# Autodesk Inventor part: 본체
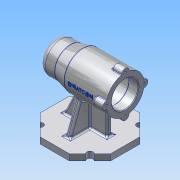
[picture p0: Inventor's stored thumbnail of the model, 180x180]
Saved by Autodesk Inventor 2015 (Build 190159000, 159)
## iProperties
Created: 2019-12
Part Number: 본체
Material: 알루미늄 6061
Document SubType Name: Modeling
Designer: user
Density: 2.7 g/cm^3
Appearance: 알루미늄 - 평지
Mass: 725.94 g
Surface Area: 714.643 cm^2
Volume: 268.867 cm^3
Author: user
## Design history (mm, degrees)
sketch "스케치2"
  geometry: L1 (-80.885, 0)-(78.814, 0) reference; L2 (0, -6)-(0, 36) reference; L3 (-56, 0)-(56, 0); L4 (-56, 0)-(-31, 0); L5 (-31, 0)-(-31, 25); L6 (-31, 25)-(-46, 25); L7 (-56, 15)-(-56, 0); L8 (-31, 0)-(-11, 0); L9 (-11, 0)-(-11, 30); L10 (-31, 25)-(-31, 0); L11 (-11, 0)-(56, 0); L12 (56, 0)-(56, 30); L13 (56, 30)-(-11, 30); L14 (-11, 30)-(-11, 0); L15 (-31, 25)-(-11, 30); A1 r 10 centre (-46, 15) between (-46, 25) and (-56, 15); 2 further points
  constraints: 26 end point, 5 parallel, 4 horizontal, 3 perpendicular, 2 point on circle, 2 point on line, 2 tangent, 1 centre point, 1 collinear, 1 symmetric about line
  dimensions: "d0" = 112 distance of L3.start L3.end; "d1" = 50 diameter of L6 L3; "d2" = 25 distance of L5.end point (-56, 25); "d3" = 45 distance between parallel lines of L7 L9; "d6" = 60 diameter of L9.end L3; "d7" = 112 distance between parallel lines of L7 L12; "d8" = 10 radius of A1
revolve "회전1" sketch "스케치2" stored, may be unused: angle "d9" = 90 deg
sketch "스케치3"
  geometry: L1 (-56, -15)-(-56, 15) reference; L2 (-46, 25)-(-31, 25) reference; L3 (-31, 25)-(-11, 30) reference; L4 (-11, 30)-(56, 30) reference; L5 (56, 30)-(56, -30) reference; L6 (56, -30)-(-11, -30) reference; L7 (-11, -30)-(-31, -25) reference; L8 (-31, -25)-(-46, -25) reference; L9 (-80.885, 0)-(78.814, 0) reference; L10 (-56, 0)-(56, 0); L11 (56, 0)-(41, 0); L12 (41, 0)-(41, 21); L13 (41, 21)-(56, 21); L14 (56, 21)-(56, 0); L15 (41, 0)-(-13, 0); L16 (-13, 0)-(-13, 21); L17 (-10, 24)-(38, 24); L18 (41, 21)-(41, 0); L19 (-13, 0)-(-25, 0); L20 (-25, 0)-(-25, 20.7); L21 (-24.7, 21)-(-13, 21); L22 (-13, 21)-(-13, 0); L23 (-25, 0)-(-43, 0); L24 (-43, 0)-(-43, 17.2); L25 (-42.7, 17.5)-(-25, 17.5); L26 (-25, 17.5)-(-25, 0); L27 (-43, 0)-(-47, 0); L28 (-47, 0)-(-47, 15.7); L29 (-46.7, 16)-(-43, 16); L30 (-43, 16)-(-43, 0); L31 (-47, 0)-(-50, 0); L32 (-50, 0)-(-50, 7.5); L33 (-47, 10.5)-(-47, 10.5); L34 (-47, 10.5)-(-47, 0); A1 r 10 centre (-46, 15) between (-46, 25) and (-56, 15) reference; A2 r 10 centre (-46, -15) between (-56, -15) and (-46, -25) reference; A3 r 0.3 centre (-46.7, 15.7) between (-46.7, 16) and (-47, 15.7); A4 r 0.3 centre (-42.7, 17.2) between (-42.7, 17.5) and (-43, 17.2); A5 r 0.3 centre (-24.7, 20.7) between (-24.7, 21) and (-25, 20.7); A6 r 3 centre (-47, 7.5) between (-47, 10.5) and (-50, 7.5); A7 r 3 centre (-10, 21) between (-10, 24) and (-13, 21); A8 r 3 centre (38, 21) between (41, 21) and (38, 24); 7 further points
  constraints: 50 end point, 12 parallel, 12 point on circle, 12 point on line, 12 tangent, 7 perpendicular, 6 centre point, 6 horizontal, 4 equal radius, 2 midpoint, 1 collinear
  dimensions: "d11" = 42 diameter of L13 L9; "d12" = 48 diameter of L17 L9; "d13" = 15 distance of L12.end L13.end; "d14" = 54 distance of point (-13, 24) point (41, 24); "d15" = 12 distance of point (-25, 21) L21.end; "d16" = 42 diameter of L21 L9; "d17" = 18 distance of point (-43, 17.5) L25.end; "d18" = 35 diameter of L25 L9; "d19" = 32 diameter of L29 L9; "d20" = 21 diameter of L33 L10; "d21" = 3 distance of point (-50, 10.5) L33.end; "d22" = 4 distance of point (-47, 16) L29.end; "d23" = 0.3 radius of A3; "d24" = 3 radius of A6
revolve "회전2" sketch "스케치3" stored, may be unused: angle "d25" = 90 deg
node "작업 평면1"
sketch "스케치4"
  geometry: L1 (0, -42)-(0, 42) reference; L2 (78.4, 0)-(-78.4, 0) reference; L3 (23.196, -56)-(-23.196, -56); L4 (-56, -23.196)-(-56, 23.196); L5 (-23.196, 56)-(23.196, 56); L6 (56, 23.196)-(56, -23.196); L7 (56, 23.196)-(23.196, 56); L8 (-56, 23.196)-(-23.196, 56); L9 (56, -23.196)-(23.196, -56); L10 (-56, -23.196)-(-23.196, -56); C1 r 56 at (0, 0); 1 further point
  constraints: 16 end point, 6 symmetric about line, 5 tangent, 2 parallel, 1 centre point, 1 coincident, 1 horizontal, 1 perpendicular
  dimensions: "d28" = 112 diameter of C1; "d30" = 45 deg angle of L7 L2
extrude "돌출1" join sketch "스케치4" distance "d31" = 10; taper "d32" = 0 deg
sketch "스케치5" dims "d33" = 112
  geometry: L1 (-56, -23.196)-(-23.196, -56) reference; C1 r 5 at (-39.598, -39.598); C2 r 5 at (39.598, -39.598); C3 r 5 at (39.598, 39.598); C4 r 5 at (-39.598, 39.598); 2 further points
  constraints: 4 centre point, 1 coincident, 1 midpoint, 12 other
  dimensions: "d34" = 10 diameter of C1; "d37" = 360 deg dimension on point (0, 0) C1.centre (derived)
extrude "돌출2" cut sketch "스케치5" distance "d39" = 10; taper "d40" = 0 deg
sketch "스케치6"
  geometry: L1 (-56, 23.196)-(-56, -23.196) reference; L2 (56, -23.196)-(56, 23.196) reference; L3 (43.134, 36.062)-(56, 23.196) reference; L4 (56, 23.196)-(56, -23.196) reference; L5 (56, -23.196)-(43.134, -36.062) reference; L6 (36.062, -43.134)-(23.196, -56) reference; L7 (23.196, -56)-(-23.196, -56) reference; L8 (-23.196, -56)-(-36.062, -43.134) reference; L9 (-43.134, -36.062)-(-56, -23.196) reference; L10 (-56, -23.196)-(-56, 23.196) reference; L11 (-56, 23.196)-(-43.134, 36.062) reference; L12 (-36.062, 43.134)-(-23.196, 56) reference; L13 (-23.196, 56)-(23.196, 56) reference; L14 (23.196, 56)-(36.062, 43.134) reference; L15 (78.4, 0)-(-78.4, 0) reference; L16 (0, 78.4)-(0, -78.4) reference; L17 (31, -4)-(-38, -4); L18 (-38, -4)-(-38, 4); L19 (-38, 4)-(31, 4); L20 (31, 4)-(31, -4); A1 r 5 centre (39.598, 39.598) between (36.062, 43.134) and (43.134, 36.062) reference; A2 r 5 centre (39.598, -39.598) between (43.134, -36.062) and (36.062, -43.134) reference; A3 r 5 centre (-39.598, -39.598) between (-36.062, -43.134) and (-43.134, -36.062) reference; A4 r 5 centre (-39.598, 39.598) between (-43.134, 36.062) and (-36.062, 43.134) reference; 1 further point
  constraints: 8 end point, 2 parallel, 1 horizontal, 1 perpendicular, 1 other
  dimensions: "d41" = 8 distance of L19.end L17.start; "d42" = 18 distance between parallel lines of L1 L18; "d43" = 25 distance between parallel lines of L20 L2
extrude "돌출3" join sketch "스케치6" stored distance "d44" = 10; taper "d45" = 0 deg
feature "면 기울기1" dims angle "d46" = 25 deg
sketch "스케치8"
  geometry: L1 (-29.732, -4)-(-70, -4) reference; L2 (-70, -4)-(-70, -56) reference; L3 (-70, -56)-(-80, -56) reference; L4 (-80, -56)-(-80, 56) reference; L5 (-80, 56)-(-70, 56) reference; L6 (-70, 56)-(-70, 4) reference; L7 (-70, 4)-(-29.732, 4) reference; L8 (-70, 36)-(-23.234, 18.979); L9 (-102, 0)-(52, 0) reference; L10 (-70, 36)-(-70, 4); L11 (-70, 4)-(-29.732, 4); C1 r 24 at (0, 0) reference; A1 r 30 centre (0, 0) between (-29.732, -4) and (-29.732, 4) reference; A2 r 30 centre (0, 0) between (-23.234, 18.979) and (-29.732, 4); 1 further point
  constraints: 6 end point, 3 point on circle, 1 centre point, 1 perpendicular, 1 point on line, 1 vertical
  dimensions: "d50" = 110 deg angle of L8 L6; "d51" = 20 distance of L8.start L5.end; "d52" = 30 radius of A2
extrude "돌출4" join sketch "스케치8" stored distance "d53" = 8; taper "d54" = 0 deg
sketch "스케치9"
  geometry: L1 (0, -102)-(0, 52) reference; C1 r 6 at (0, 30); 1 further point
  constraints: 1 centre point, 1 point on line, 1 vertical alignment, 1 other
  dimensions: "d56" = 12 diameter of C1
extrude "돌출5" join sketch "스케치9" distance "d57" = 16; taper "d58" = 0 deg
hole "구멍1" diameter "d64" = 3.242; stored, may be unused: countersink angle "d68" = 90 deg, drill point angle "d70" = 118 deg; dims "d65" = 8, "d66" = 4, "d67" = 2, "d69" = 11, "d88" = 10, "d89" = 10
fillet "모깎기1" dims "d74" = 3
fillet "모깎기2" dims "d75" = 1
fillet "모깎기3" dims "d76" = 3
fillet "모깎기4" dims "d77" = 1
fillet "모깎기5" dims "d78" = 3
fillet "모깎기6" dims "d79" = 3
fillet "모깎기7" dims "d80" = 3
fillet "모깎기8" dims "d81" = 3
chamfer "모따기1" distance "d82" = 1; stored, may be unused: second distance "d83" = 2, angle "d84" = 45 deg
node "작업 평면2"
sketch "스케치10"
  geometry: L1 (33.5, 6.771)-(33.5, 29.226) reference; L2 (-100.9, 0)-(55.9, 0) reference; 2 further points
  constraints: 1 point on line, 1 other
  dimensions: "d85" = 41 distance from line of point (-7.5, 0) L1
feature "엠보싱1" sketch "스케치10" dims "d0" = 112, "d1" = 50, "d2" = 25, "d3" = 45, "d6" = 60, "d7" = 112, "d8" = 10, "d86" = 0.5, "d87" = 0
node "솔리드1"
mirror "대칭1"
pattern_circular "원형 패턴1" dims angle "d60" = 360 deg
pattern_circular "원형 패턴2" dims angle "d72" = 360 deg
node "절단 모서리 투영1"
node "절단 모서리 투영2"
node "절단 모서리 투영6"
